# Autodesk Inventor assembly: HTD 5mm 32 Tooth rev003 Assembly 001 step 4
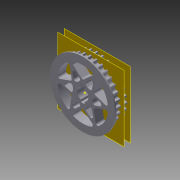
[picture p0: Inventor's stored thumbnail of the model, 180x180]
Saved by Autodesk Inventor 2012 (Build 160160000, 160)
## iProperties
Created: 2012-01
Part Number: HTD 5mm 32 Tooth rev003 Assembly 001 step 4
Document SubType Name: Assembly
Designer: Alex
Author: Alex
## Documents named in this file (3)
- C:\Users\Owner\Documents\Robotics\Mechanical Design\Parts\pulley\HTD\32\HTD 5mm 32 Tooth rev003 Assembly 001 step 4.iam
- C:\Users\Owner\Documents\Robotics\Mechanical Design\Parts\pulley\HTD\32\HTD 5mm 32 Tooth rev003 step 2.ipt
- C:\Users\Owner\Documents\Robotics\Mechanical Design\Parts\pulley\HTD\32\HTD 5mm 32 Tooth Flange_rev001.ipt
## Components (2 placed, 2 different names)
1. HTD 5mm 32 Tooth rev003 step 2:1 — Mate:1, Mate:2, Flush:1, Flush:2
2. HTD 5mm 32 Tooth Flange_rev001:1 — Mate:1, Mate:2
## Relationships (4: Mate 2, Flush 2)
- Mate:1: HTD 5mm 32 Tooth rev003 step 2:1 ↔ HTD 5mm 32 Tooth Flange_rev001:1
- Mate:2: HTD 5mm 32 Tooth rev003 step 2:1 ↔ HTD 5mm 32 Tooth Flange_rev001:1
- Flush:1: HTD 5mm 32 Tooth rev003 step 2:1
- Flush:2: HTD 5mm 32 Tooth rev003 step 2:1
